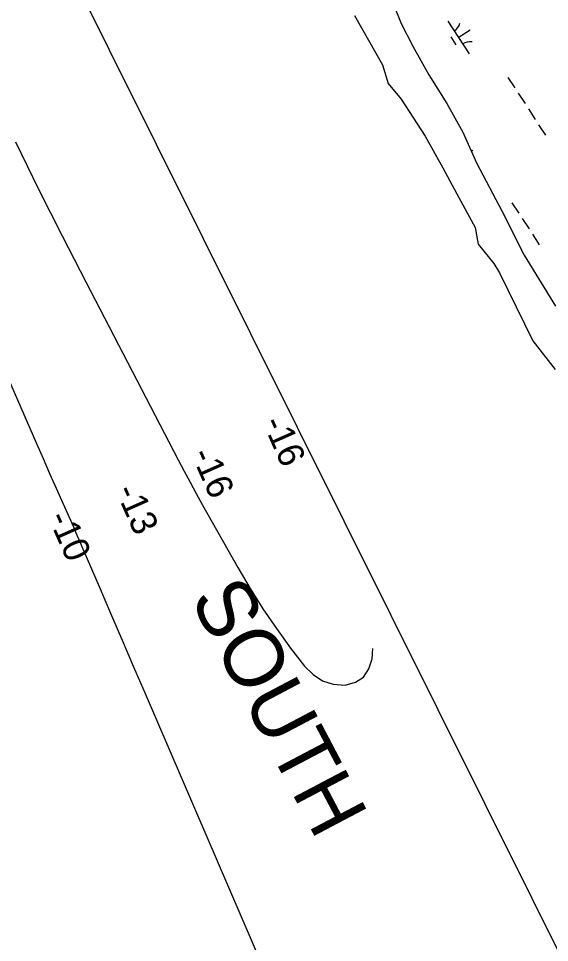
# Model space of a CAD drawing. Extents: x 3953924 to 3974542, y 193747 to 216192.
# Drawn here: x 3960676 to 3961355, y 208758 to 209938 of the extents above; entities that cross this region are included whole.
import ezdxf

# ---------------------------------------------------------------- set-up
doc = ezdxf.new("R2010")
doc.units = 0
for name, color, linetype in [('V-RIVR-EDGE', 7, 'Continuous'), ('V-RIVR-IDEN', 7, 'Continuous'), ('V-RIVR-RANG', 7, 'Continuous'), ('V-TOPO-DPTH', 7, 'Continuous'), ('V-TOPO-MINR', 7, 'Continuous'), ('V-WETL-SWMP', 7, 'Continuous')]:
    doc.layers.add(name, color=color, linetype=linetype)

msp = doc.modelspace()

# ---------------------------------------------------------------- linework, layer by layer
at = {"layer": 'V-RIVR-EDGE'}
msp.add_lwpolyline([(3961105.9, 209942.1), (3961141.5, 209879.2), (3961148.6, 209855.4), (3961165.2, 209835.3), (3961196.1, 209787.8), (3961218.6, 209747.4), (3961236.4, 209714.2), (3961260.2, 209671.4), (3961263.8, 209650.1), (3961283.9, 209625.1), (3961291.1, 209613.2), (3961333.8, 209526.6), (3961362.3, 209489.8)], dxfattribs=at)
at = {"layer": 'V-TOPO-DPTH'}
for points in [[(3961753.3, 207971.3), (3960371.5, 210740.9)], [(3960498.2, 209855.2), (3960699.1, 209395.2), (3960707.5, 209376.1), (3960715.8, 209357.1), (3960724.2, 209338.1), (3960732.7, 209319.1), (3960746.2, 209288.8), (3960747.9, 209284.9), (3960749.5, 209281.1), (3960751.2, 209277.3), (3960752.9, 209273.4), (3960779.1, 209212.7), (3960793.8, 209178.4), (3960808.6, 209144.2), (3960823.3, 209110), (3960838.1, 209075.7), (3961052.4, 208577.9)]]:
    msp.add_lwpolyline(points, dxfattribs=at)
at = {"layer": 'V-TOPO-MINR'}
for points in [[(3960498.2, 209855.2), (3960699.1, 209395.2), (3960707.5, 209376.1), (3960715.8, 209357.1), (3960724.2, 209338.1), (3960732.7, 209319.1), (3960746.2, 209288.8), (3960747.9, 209284.9), (3960749.5, 209281.1), (3960751.2, 209277.3), (3960752.9, 209273.4), (3960779.1, 209212.7), (3960793.8, 209178.4), (3960808.6, 209144.2), (3960823.3, 209110), (3960838.1, 209075.7), (3961052.4, 208577.9)], [(3960672.1, 209780.6), (3960701.7, 209720.4), (3960731.9, 209660.5), (3960762.5, 209600.8), (3960880.3, 209374.3), (3960887.8, 209360), (3960895.4, 209345.8), (3960903.1, 209331.6), (3960911, 209317.5), (3960956.4, 209236.8), (3960972.1, 209210.2), (3960988.5, 209184.2), (3961005.9, 209158.8), (3961024, 209133.9), (3961041.8, 209110.6), (3961052.7, 209100.1), (3961064.8, 209092.1), (3961078.6, 209088), (3961093.7, 209086.5), (3961106.8, 209090.4), (3961117.4, 209096.9), (3961124.1, 209107.3), (3961128.3, 209120.3), (3961129.2, 209133.2)]]:
    msp.add_lwpolyline(points, dxfattribs=at)
at = {"layer": 'V-WETL-SWMP'}
for p, q in [((3961154, 209960.5), (3961165.5, 209932)), ((3961224.9, 209934.9), (3961252.2, 209893)), ((3961165.5, 209932), (3961180.3, 209902.9)), ((3961238.5, 209913.9), (3961253.6, 209923.7)), ((3961228.8, 209914.7), (3961235.3, 209904.7)), ((3961180.3, 209902.9), (3961200.6, 209866.5)), ((3961200.6, 209866.5), (3961224, 209829.9)), ((3961203.7, 209861.7), (3961205, 209859.6)), ((3961302, 209863), (3961310.7, 209849.6)), ((3961315.1, 209842.9), (3961323.8, 209829.5)), ((3961224, 209829.9), (3961244.2, 209792.9)), ((3961328.1, 209822.8), (3961336.9, 209809.3)), ((3961341.2, 209802.6), (3961350, 209789.2)), ((3961244.2, 209792.9), (3961261.7, 209754)), ((3961255.1, 209768.7), (3961257.1, 209770)), ((3961261.7, 209754), (3961294.4, 209691.7)), ((3961307, 209702.9), (3961315.8, 209689.5)), ((3961294.4, 209691.7), (3961322.7, 209635.8)), ((3961320.1, 209682.8), (3961328.9, 209669.4)), ((3961333.2, 209662.6), (3961342, 209649.2)), ((3961322.7, 209635.8), (3961362.7, 209570.8))]:
    msp.add_line(p, q, dxfattribs=at)
for centre, start, end in [((3961223.7, 209937.2), 302.2901, 343.8338), ((3961253.8, 209890.9), 82.2901, 123.8337)]:
    msp.add_arc(centre, 17.6, start, end, dxfattribs=at)

# ---------------------------------------------------------------- texts
at = {"layer": 'V-RIVR-IDEN'}
msp.add_text('SOUTH', height=75, rotation=297.756, dxfattribs=at).set_placement((3960894.6, 209197.4))
at = {"layer": 'V-RIVR-RANG'}
for s, p in [('-16', (3960987.7, 209422)), ('-16', (3960896.3, 209381.5)), ('-13', (3960799.6, 209335)), ('-10', (3960713.3, 209300.8))]:
    msp.add_text(s, height=33.5, rotation=293.8998, dxfattribs=at).set_placement(p)

doc.saveas('drawing.dxf')
